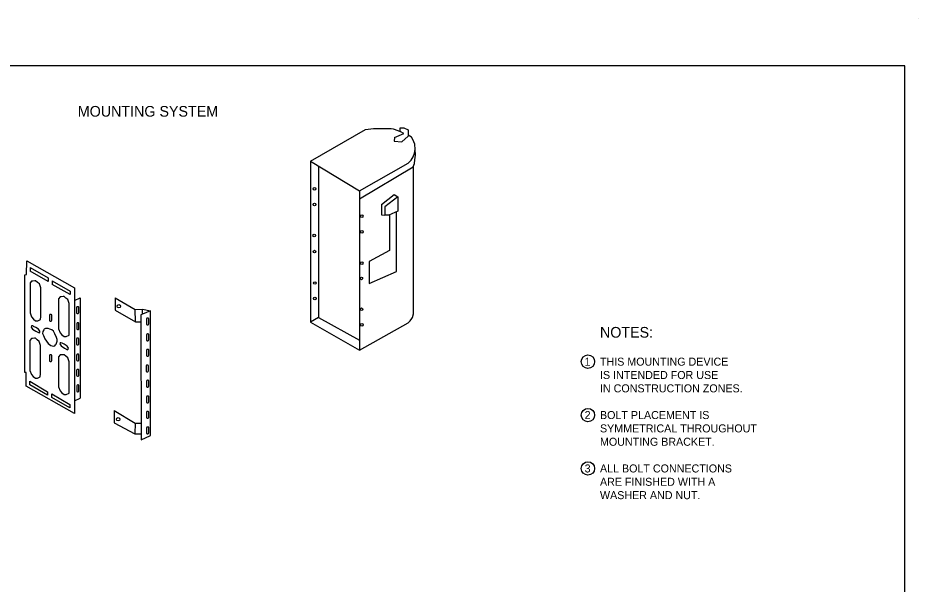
# Model space of a CAD drawing. Extents: x 49991.4 to 50021, y 49987.6 to 50011.4.
# Drawn here: x 50014.29 to 50021.04, y 50004.28 to 50008.52 of the extents above; entities that cross this region are included whole.
import ezdxf

# ---------------------------------------------------------------- set-up
doc = ezdxf.new("R2010")
doc.units = 0
for name, color, linetype in [('Level 1', 7, 'Continuous'), ('Level 2', 7, 'Continuous'), ('Level 3', 7, 'Continuous')]:
    doc.layers.add(name, color=color, linetype=linetype)

msp = doc.modelspace()

# ---------------------------------------------------------------- linework, layer by layer
at = {"layer": 'Level 1'}
for p, q in [((50021.0378, 50008.5236), (50021.0378, 50008.5236)), ((50016.4827, 50007.4512), (50016.8949, 50007.6874)), ((50017.1542, 50007.6723), (50017.1542, 50007.7013)), ((50017.1542, 50007.7013), (50017.1831, 50007.7013)), ((50017.1831, 50007.7013), (50017.2144, 50007.685)), ((50017.2144, 50007.685), (50017.2144, 50007.6381)), ((50017.1125, 50007.6295), (50017.1102, 50007.6017)), ((50017.1125, 50007.6295), (50017.1831, 50007.6573)), ((50017.1831, 50007.6573), (50017.1542, 50007.6723)), ((50017.1672, 50007.5969), (50017.2144, 50007.6381)), ((50017.1102, 50007.6017), (50017.1672, 50007.5969)), ((50016.4827, 50007.4512), (50016.8485, 50007.2289)), ((50016.4827, 50007.4512), (50016.4827, 50006.2451)), ((50016.8485, 50007.2289), (50017.2144, 50007.4373)), ((50016.8485, 50007.1702), (50017.2515, 50007.4082)), ((50016.8485, 50007.2289), (50016.8485, 50006.0346)), ((50017.0153, 50007.127), (50017.1102, 50007.2011)), ((50017.1357, 50007.1849), (50017.0384, 50007.1085)), ((50017.1102, 50007.2011), (50017.1357, 50007.1849)), ((50017.1357, 50007.1849), (50017.1357, 50007.076)), ((50017.0384, 50007.1085), (50017.0384, 50007.0459)), ((50017.1357, 50007.076), (50017.0685, 50007.0459)), ((50017.1264, 50006.6257), (50017.1264, 50007.0719)), ((50017.0685, 50007.0459), (50017.0361, 50007.0459)), ((50017.0743, 50007.0485), (50017.0743, 50006.782)), ((50017.0743, 50006.782), (50016.9215, 50006.6986)), ((50014.3529, 50006.603), (50014.3552, 50006.7049)), ((50014.3552, 50006.7049), (50014.7118, 50006.5011)), ((50016.9215, 50006.6986), (50016.9215, 50006.5342)), ((50014.339, 50006.6007), (50014.3529, 50006.603)), ((50014.339, 50005.8689), (50014.339, 50006.6007)), ((50014.3807, 50006.6551), (50014.515, 50006.5763)), ((50014.3807, 50006.6551), (50014.3807, 50006.6278)), ((50014.515, 50006.5509), (50014.3807, 50006.6278)), ((50016.9215, 50006.5342), (50017.1264, 50006.6257)), ((50014.515, 50006.5763), (50014.515, 50006.5509)), ((50014.5451, 50006.5555), (50014.6794, 50006.4768)), ((50014.5451, 50006.5555), (50014.5451, 50006.5282)), ((50014.6794, 50006.4513), (50014.5451, 50006.5282)), ((50014.6794, 50006.4768), (50014.6794, 50006.4513)), ((50014.7118, 50006.5011), (50014.7118, 50006.4061)), ((50014.7118, 50006.4061), (50014.7558, 50006.427)), ((50014.7118, 50006.4061), (50014.7118, 50005.5599)), ((50014.7558, 50006.427), (50014.7558, 50005.6767)), ((50015.016, 50006.4264), (50015.1665, 50006.3407)), ((50015.016, 50006.4264), (50015.016, 50006.3338)), ((50015.016, 50006.3338), (50015.1689, 50006.2481)), ((50015.1665, 50006.3407), (50015.2223, 50006.3424)), ((50015.1689, 50006.2481), (50015.1665, 50006.3407)), ((50015.2223, 50006.3424), (50015.2823, 50006.3292)), ((50015.2224, 50006.3053), (50015.2223, 50006.3424)), ((50015.2823, 50006.3292), (50015.2229, 50006.3053)), ((50015.2823, 50005.396), (50015.2823, 50006.3292)), ((50015.2229, 50006.3053), (50015.2096, 50006.2997)), ((50015.2096, 50006.2997), (50015.2096, 50006.2468)), ((50016.5429, 50006.2795), (50016.4827, 50006.2451)), ((50016.5429, 50006.2795), (50016.8485, 50006.1112)), ((50015.1689, 50006.2481), (50015.2096, 50006.2468)), ((50015.2096, 50006.2468), (50015.2113, 50005.3637)), ((50016.4827, 50006.2451), (50016.8485, 50006.0346)), ((50014.3506, 50005.8689), (50014.339, 50005.8689)), ((50014.3506, 50005.7647), (50014.3506, 50005.8689)), ((50014.7118, 50005.5599), (50014.3506, 50005.7647)), ((50014.7118, 50005.6559), (50014.7558, 50005.6767)), ((50015.0091, 50005.5835), (50015.1665, 50005.4886)), ((50015.0091, 50005.5835), (50015.0091, 50005.4909)), ((50015.0091, 50005.4909), (50015.1649, 50005.4075)), ((50015.1665, 50005.4886), (50015.1649, 50005.4075)), ((50015.1665, 50005.4886), (50015.2111, 50005.4874)), ((50015.1649, 50005.4075), (50015.2112, 50005.4075)), ((50015.2113, 50005.3637), (50015.2823, 50005.396))]:
    msp.add_line(p, q, dxfattribs=at)
for points in [[(50020.9378, 50008.1646), (50009.7374, 50008.1646), (50009.7374, 49999.8856), (50020.9378, 49999.8856)], [(50014.3792, 50006.5387), (50014.3792, 50006.3141), (50014.3908, 50006.284), (50014.4047, 50006.2678), (50014.4209, 50006.2562), (50014.4371, 50006.2562), (50014.458, 50006.2655), (50014.4603, 50006.2886), (50014.4603, 50006.5017), (50014.4487, 50006.5318), (50014.4348, 50006.5433), (50014.4209, 50006.5549), (50014.414, 50006.5549), (50014.4001, 50006.5526), (50014.3908, 50006.5526)], [(50014.5923, 50006.4206), (50014.5923, 50006.196), (50014.6038, 50006.1659), (50014.6177, 50006.1497), (50014.634, 50006.1381), (50014.6502, 50006.1381), (50014.671, 50006.1474), (50014.6733, 50006.1705), (50014.6733, 50006.3836), (50014.6617, 50006.4137), (50014.6478, 50006.4253), (50014.634, 50006.4368), (50014.627, 50006.4368), (50014.6131, 50006.4345), (50014.6038, 50006.4345)], [(50014.7364, 50006.3607), (50014.7306, 50006.3601), (50014.7277, 50006.3538), (50014.7277, 50006.3422), (50014.7277, 50006.3294), (50014.7277, 50006.3184), (50014.7283, 50006.3127), (50014.7329, 50006.3103), (50014.737, 50006.3103), (50014.7399, 50006.3109), (50014.7434, 50006.3127), (50014.7445, 50006.3173), (50014.7445, 50006.3265), (50014.7445, 50006.3549), (50014.7445, 50006.3584), (50014.7422, 50006.359), (50014.7416, 50006.3595), (50014.7399, 50006.3601), (50014.7387, 50006.3607)], [(50014.5332, 50006.3025), (50014.5274, 50006.3019), (50014.5245, 50006.2956), (50014.5245, 50006.284), (50014.5245, 50006.2713), (50014.5245, 50006.2603), (50014.5251, 50006.2545), (50014.5297, 50006.2522), (50014.5338, 50006.2522), (50014.5367, 50006.2527), (50014.5402, 50006.2545), (50014.5413, 50006.2591), (50014.5413, 50006.2684), (50014.5413, 50006.2967), (50014.5413, 50006.3002), (50014.539, 50006.3008), (50014.5384, 50006.3014), (50014.5367, 50006.3019), (50014.5355, 50006.3025)], [(50015.2603, 50006.2747), (50015.2545, 50006.2742), (50015.2516, 50006.2678), (50015.2516, 50006.2562), (50015.2516, 50006.2435), (50015.2516, 50006.2325), (50015.2522, 50006.2267), (50015.2569, 50006.2244), (50015.2609, 50006.2244), (50015.2638, 50006.225), (50015.2673, 50006.2267), (50015.2684, 50006.2313), (50015.2684, 50006.2406), (50015.2684, 50006.2689), (50015.2684, 50006.2724), (50015.2661, 50006.273), (50015.2655, 50006.2736), (50015.2638, 50006.2742), (50015.2626, 50006.2747)], [(50014.3897, 50006.2163), (50014.3879, 50006.2087), (50014.3978, 50006.1937), (50014.4232, 50006.1769), (50014.4464, 50006.1647), (50014.4516, 50006.1682), (50014.4528, 50006.1769), (50014.4423, 50006.192), (50014.4215, 50006.2058), (50014.4059, 50006.2134), (50014.396, 50006.2174)], [(50014.4823, 50006.1873), (50014.4759, 50006.1752), (50014.473, 50006.1601), (50014.4794, 50006.1439), (50014.4904, 50006.119), (50014.5141, 50006.0843), (50014.5355, 50006.071), (50014.5541, 50006.0663), (50014.5656, 50006.0686), (50014.5703, 50006.0744), (50014.5743, 50006.0814), (50014.5772, 50006.0878), (50014.5813, 50006.1034), (50014.5813, 50006.1161), (50014.5766, 50006.1294), (50014.5639, 50006.1566), (50014.5541, 50006.1769), (50014.5413, 50006.1873), (50014.5263, 50006.1937), (50014.5147, 50006.1972), (50014.5049, 50006.1972), (50014.495, 50006.1966), (50014.4858, 50006.1931)], [(50014.7376, 50006.2409), (50014.7318, 50006.2403), (50014.7289, 50006.2339), (50014.7289, 50006.2223), (50014.7289, 50006.2096), (50014.7289, 50006.1986), (50014.7295, 50006.1928), (50014.7341, 50006.1905), (50014.7382, 50006.1905), (50014.741, 50006.1911), (50014.7445, 50006.1928), (50014.7457, 50006.1975), (50014.7457, 50006.2067), (50014.7457, 50006.2351), (50014.7457, 50006.2386), (50014.7434, 50006.2391), (50014.7428, 50006.2397), (50014.741, 50006.2403), (50014.7399, 50006.2409)], [(50014.3769, 50006.108), (50014.3769, 50005.8834), (50014.3885, 50005.8533), (50014.4024, 50005.8371), (50014.4186, 50005.8255), (50014.4348, 50005.8255), (50014.4556, 50005.8348), (50014.458, 50005.8579), (50014.458, 50006.071), (50014.4464, 50006.1011), (50014.4325, 50006.1126), (50014.4186, 50006.1242), (50014.4117, 50006.1242), (50014.3978, 50006.1219), (50014.3885, 50006.1219)], [(50014.7364, 50006.1245), (50014.7306, 50006.1239), (50014.7277, 50006.1176), (50014.7277, 50006.106), (50014.7277, 50006.0933), (50014.7277, 50006.0823), (50014.7283, 50006.0765), (50014.7329, 50006.0741), (50014.737, 50006.0741), (50014.7399, 50006.0747), (50014.7434, 50006.0765), (50014.7445, 50006.0811), (50014.7445, 50006.0904), (50014.7445, 50006.1187), (50014.7445, 50006.1222), (50014.7422, 50006.1228), (50014.7416, 50006.1234), (50014.7399, 50006.1239), (50014.7387, 50006.1245)], [(50015.2603, 50006.1566), (50015.2545, 50006.1561), (50015.2516, 50006.1497), (50015.2516, 50006.1381), (50015.2516, 50006.1254), (50015.2516, 50006.1144), (50015.2522, 50006.1086), (50015.2569, 50006.1063), (50015.2609, 50006.1063), (50015.2638, 50006.1069), (50015.2673, 50006.1086), (50015.2684, 50006.1132), (50015.2684, 50006.1225), (50015.2684, 50006.1509), (50015.2684, 50006.1543), (50015.2661, 50006.1549), (50015.2655, 50006.1555), (50015.2638, 50006.1561), (50015.2626, 50006.1566)], [(50014.6038, 50006.0898), (50014.6021, 50006.0823), (50014.612, 50006.0672), (50014.6374, 50006.0504), (50014.6606, 50006.0383), (50014.6658, 50006.0417), (50014.6669, 50006.0504), (50014.6565, 50006.0655), (50014.6357, 50006.0794), (50014.6201, 50006.0869), (50014.6102, 50006.0909)], [(50014.5332, 50006), (50014.5274, 50005.9995), (50014.5245, 50005.9931), (50014.5245, 50005.9815), (50014.5245, 50005.9688), (50014.5245, 50005.9578), (50014.5251, 50005.952), (50014.5297, 50005.9497), (50014.5338, 50005.9497), (50014.5367, 50005.9503), (50014.5402, 50005.952), (50014.5413, 50005.9566), (50014.5413, 50005.9659), (50014.5413, 50005.9943), (50014.5413, 50005.9977), (50014.539, 50005.9983), (50014.5384, 50005.9989), (50014.5367, 50005.9995), (50014.5355, 50006)], [(50014.5923, 50005.9853), (50014.5923, 50005.7607), (50014.6038, 50005.7306), (50014.6177, 50005.7144), (50014.634, 50005.7028), (50014.6502, 50005.7028), (50014.671, 50005.712), (50014.6733, 50005.7352), (50014.6733, 50005.9482), (50014.6617, 50005.9783), (50014.6478, 50005.9899), (50014.634, 50006.0015), (50014.627, 50006.0015), (50014.6131, 50005.9992), (50014.6038, 50005.9992)], [(50014.737, 50006.0053), (50014.7312, 50006.0047), (50014.7283, 50005.9983), (50014.7283, 50005.9867), (50014.7283, 50005.974), (50014.7283, 50005.963), (50014.7289, 50005.9572), (50014.7335, 50005.9549), (50014.7376, 50005.9549), (50014.7405, 50005.9555), (50014.7439, 50005.9572), (50014.7451, 50005.9618), (50014.7451, 50005.9711), (50014.7451, 50005.9995), (50014.7451, 50006.0029), (50014.7428, 50006.0035), (50014.7422, 50006.0041), (50014.7405, 50006.0047), (50014.7393, 50006.0053)], [(50015.2603, 50006.0409), (50015.2545, 50006.0403), (50015.2516, 50006.0339), (50015.2516, 50006.0223), (50015.2516, 50006.0096), (50015.2516, 50005.9986), (50015.2522, 50005.9928), (50015.2569, 50005.9905), (50015.2609, 50005.9905), (50015.2638, 50005.9911), (50015.2673, 50005.9928), (50015.2684, 50005.9974), (50015.2684, 50006.0067), (50015.2684, 50006.0351), (50015.2684, 50006.0385), (50015.2661, 50006.0391), (50015.2655, 50006.0397), (50015.2638, 50006.0403), (50015.2626, 50006.0409)], [(50015.258, 50005.9228), (50015.2522, 50005.9222), (50015.2493, 50005.9158), (50015.2493, 50005.9042), (50015.2493, 50005.8915), (50015.2493, 50005.8805), (50015.2499, 50005.8747), (50015.2545, 50005.8724), (50015.2586, 50005.8724), (50015.2615, 50005.873), (50015.265, 50005.8747), (50015.2661, 50005.8793), (50015.2661, 50005.8886), (50015.2661, 50005.917), (50015.2661, 50005.9204), (50015.2638, 50005.921), (50015.2632, 50005.9216), (50015.2615, 50005.9222), (50015.2603, 50005.9228)], [(50014.737, 50005.8912), (50014.7312, 50005.8906), (50014.7283, 50005.8843), (50014.7283, 50005.8727), (50014.7283, 50005.86), (50014.7283, 50005.849), (50014.7289, 50005.8432), (50014.7335, 50005.8408), (50014.7376, 50005.8408), (50014.7405, 50005.8414), (50014.7439, 50005.8432), (50014.7451, 50005.8478), (50014.7451, 50005.8571), (50014.7451, 50005.8854), (50014.7451, 50005.8889), (50014.7428, 50005.8895), (50014.7422, 50005.8901), (50014.7405, 50005.8906), (50014.7393, 50005.8912)], [(50015.2603, 50005.8093), (50015.2545, 50005.8087), (50015.2516, 50005.8024), (50015.2516, 50005.7908), (50015.2516, 50005.778), (50015.2516, 50005.767), (50015.2522, 50005.7612), (50015.2569, 50005.7589), (50015.2609, 50005.7589), (50015.2638, 50005.7595), (50015.2673, 50005.7612), (50015.2684, 50005.7659), (50015.2684, 50005.7751), (50015.2684, 50005.8035), (50015.2684, 50005.807), (50015.2661, 50005.8076), (50015.2655, 50005.8081), (50015.2638, 50005.8087), (50015.2626, 50005.8093)], [(50014.7376, 50005.7743), (50014.7318, 50005.7737), (50014.7289, 50005.7673), (50014.7289, 50005.7557), (50014.7289, 50005.743), (50014.7289, 50005.732), (50014.7295, 50005.7262), (50014.7341, 50005.7239), (50014.7382, 50005.7239), (50014.741, 50005.7245), (50014.7445, 50005.7262), (50014.7457, 50005.7309), (50014.7457, 50005.7401), (50014.7457, 50005.7685), (50014.7457, 50005.772), (50014.7434, 50005.7725), (50014.7428, 50005.7731), (50014.741, 50005.7737), (50014.7399, 50005.7743)], [(50015.2603, 50005.6912), (50015.2545, 50005.6906), (50015.2516, 50005.6843), (50015.2516, 50005.6727), (50015.2516, 50005.6599), (50015.2516, 50005.6489), (50015.2522, 50005.6432), (50015.2569, 50005.6408), (50015.2609, 50005.6408), (50015.2638, 50005.6414), (50015.2673, 50005.6432), (50015.2684, 50005.6478), (50015.2684, 50005.657), (50015.2684, 50005.6854), (50015.2684, 50005.6889), (50015.2661, 50005.6895), (50015.2655, 50005.69), (50015.2638, 50005.6906), (50015.2626, 50005.6912)], [(50015.2603, 50005.5754), (50015.2545, 50005.5748), (50015.2516, 50005.5685), (50015.2516, 50005.5569), (50015.2516, 50005.5442), (50015.2516, 50005.5332), (50015.2522, 50005.5274), (50015.2569, 50005.5251), (50015.2609, 50005.5251), (50015.2638, 50005.5256), (50015.2673, 50005.5274), (50015.2684, 50005.532), (50015.2684, 50005.5413), (50015.2684, 50005.5696), (50015.2684, 50005.5731), (50015.2661, 50005.5737), (50015.2655, 50005.5743), (50015.2638, 50005.5748), (50015.2626, 50005.5754)], [(50015.2603, 50005.4596), (50015.2545, 50005.4591), (50015.2516, 50005.4527), (50015.2516, 50005.4411), (50015.2516, 50005.4284), (50015.2516, 50005.4174), (50015.2522, 50005.4116), (50015.2569, 50005.4093), (50015.2609, 50005.4093), (50015.2638, 50005.4099), (50015.2673, 50005.4116), (50015.2684, 50005.4162), (50015.2684, 50005.4255), (50015.2684, 50005.4539), (50015.2684, 50005.4573), (50015.2661, 50005.4579), (50015.2655, 50005.4585), (50015.2638, 50005.4591), (50015.2626, 50005.4596)]]:
    msp.add_lwpolyline(points, close=True, dxfattribs=at)
for points in [[(50016.8949, 50007.6874), (50016.9551, 50007.6955), (50016.9863, 50007.6966), (50017.0199, 50007.6966), (50017.0616, 50007.6966), (50017.0859, 50007.6955), (50017.1021, 50007.6932), (50017.138, 50007.6804), (50017.1542, 50007.6733)], [(50017.2619, 50007.5114), (50017.2677, 50007.5395), (50017.2642, 50007.578), (50017.2503, 50007.6142), (50017.2383, 50007.6298), (50017.2144, 50007.646)], [(50017.2515, 50007.4082), (50017.2611, 50007.4341), (50017.2656, 50007.4609), (50017.2695, 50007.4953), (50017.2677, 50007.5395), (50017.2677, 50007.5395)], [(50017.2144, 50007.4373), (50017.2364, 50007.4581), (50017.2515, 50007.4824), (50017.2619, 50007.5114)], [(50016.5429, 50007.4146), (50016.5429, 50006.2795), (50016.5429, 50006.2795)], [(50017.2515, 50007.4082), (50017.2515, 50006.3026)], [(50017.0153, 50007.127), (50017.0153, 50007.0483), (50017.0361, 50007.0459)], [(50016.8485, 50006.0346), (50017.2144, 50006.2389), (50017.2306, 50006.2552), (50017.2422, 50006.2714), (50017.2468, 50006.2806), (50017.2507, 50006.2981), (50017.2515, 50006.3026), (50017.2515, 50006.3026)], [(50014.3761, 50005.8029), (50014.5104, 50005.7242), (50014.5104, 50005.6987), (50014.3761, 50005.7763), (50014.3761, 50005.8029)], [(50014.5428, 50005.708), (50014.6771, 50005.6293), (50014.6771, 50005.6038), (50014.5428, 50005.6814), (50014.5428, 50005.708)]]:
    msp.add_lwpolyline(points, dxfattribs=at)
for centre, radius in [((50016.5128, 50007.2435), 0.00996), ((50016.5128, 50007.1265), 0.00996), ((50016.8659, 50007.039), 0.00996), ((50016.8671, 50006.9216), 0.00996), ((50016.5105, 50006.895), 0.00996), ((50016.5128, 50006.7734), 0.00996), ((50016.8659, 50006.6866), 0.00996), ((50016.5139, 50006.5384), 0.00996), ((50016.8636, 50006.5731), 0.00996), ((50016.5139, 50006.4226), 0.00996), ((50015.0444, 50006.3643), 0.0131), ((50016.8647, 50006.3415), 0.00996), ((50016.8671, 50006.2246), 0.00996), ((50015.0395, 50005.5177), 0.0131)]:
    msp.add_circle(centre, radius, dxfattribs=at)
at = {"layer": 'Level 3'}
for centre in [(50018.5629, 50005.9491), (50018.5629, 50005.5491), (50018.5629, 50005.1491)]:
    msp.add_circle(centre, 0.05, dxfattribs=at)

# ---------------------------------------------------------------- texts
at = {"layer": 'Level 2'}
for s, height, p in [('MOUNTING SYSTEM', 0.08, (50014.737, 50007.7846)), ('NOTES:', 0.08, (50018.6529, 50006.1291)), ('1', 0.06, (50018.5369, 50005.9187)), ('THIS MOUNTING DEVICE', 0.06, (50018.6529, 50005.9191)), ('IS INTENDED FOR USE', 0.06, (50018.6529, 50005.8191)), ('IN CONSTRUCTION ZONES.', 0.06, (50018.6529, 50005.7191)), ('2', 0.06, (50018.5378, 50005.5191)), ('BOLT PLACEMENT IS', 0.06, (50018.6529, 50005.5191)), ('SYMMETRICAL THROUGHOUT', 0.06, (50018.6529, 50005.4191)), ('MOUNTING BRACKET.', 0.06, (50018.6529, 50005.3191)), ('3', 0.06, (50018.5377, 50005.1191)), ('ALL BOLT CONNECTIONS', 0.06, (50018.6529, 50005.1191)), ('ARE FINISHED WITH A ', 0.06, (50018.6529, 50005.0191)), ('WASHER AND NUT.', 0.06, (50018.6529, 50004.9191))]:
    msp.add_text(s, height=height, dxfattribs=at).set_placement(p)

doc.saveas('drawing.dxf')
